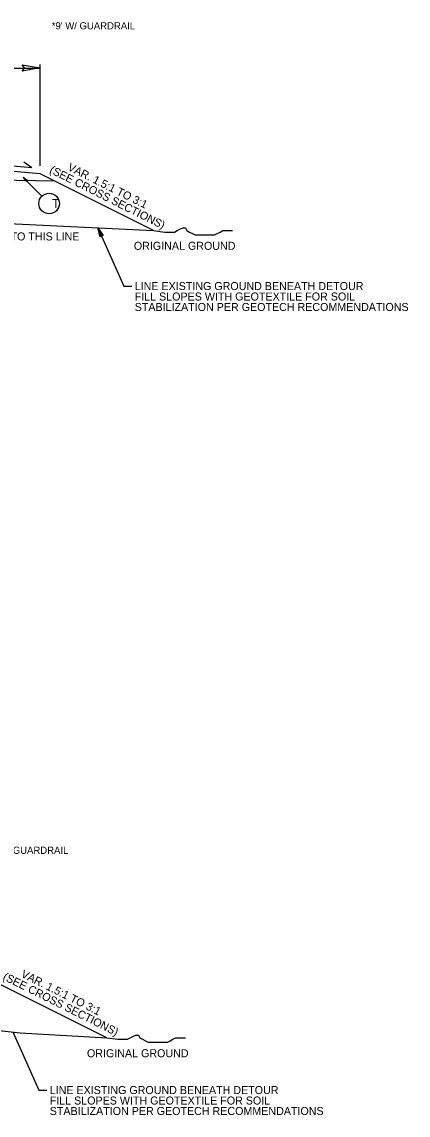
# Model space of a CAD drawing. Extents: x 1548135 to 1549339, y 868664 to 869085.
# Drawn here: x 1548385.7 to 1548422, y 868733.8 to 868836.2 of the extents above; entities that cross this region are included whole.
import ezdxf

# ---------------------------------------------------------------- set-up
doc = ezdxf.new("R2010")
doc.units = 0
for name, color, linetype in [('P_RDY_TC_Pvmt_Asphalt_Base_Course', 7, 'Continuous'), ('Prop Dimension', 7, 'Continuous'), ('Sheet_Data_Field_CELL', 7, 'Continuous'), ('Sheet_Plan', 7, 'Continuous'), ('Typical Grade Point Symbol CELL', 7, 'Continuous'), ('Typical Hinge Slope Interstate CELL', 7, 'Continuous'), ('Typical Pavement Slope Information CELL', 7, 'Continuous'), ('Typical Text General CELL', 7, 'Continuous'), ('Typical Text Grade Point CELL', 7, 'Continuous')]:
    doc.layers.add(name, color=color, linetype=linetype)

msp = doc.modelspace()

# ---------------------------------------------------------------- linework, layer by layer
at = {"layer": 'P_RDY_TC_Pvmt_Asphalt_Base_Course'}
msp.add_lwpolyline([(1548385.78, 868832.2), (1548387.47, 868831.91), (1548385.77, 868831.61), (1548385.98, 868831.91)], close=True, dxfattribs=at)
at = {"layer": 'Prop Dimension'}
for p, q in [((1548398.1, 868816.67), (1548387.47, 868821.99)), ((1548393.7, 868741.02), (1548383.06, 868746.34))]:
    msp.add_line(p, q, dxfattribs=at)
for points in [[(1548398.1, 868816.67), (1548399.14, 868816.54), (1548399.4, 868816.54), (1548399.79, 868816.54), (1548400.05, 868816.54), (1548400.31, 868816.67), (1548400.57, 868816.8), (1548400.83, 868816.93), (1548401.09, 868816.93), (1548401.22, 868816.67), (1548401.48, 868816.54), (1548401.74, 868816.41), (1548401.99, 868816.28), (1548402.25, 868816.28), (1548402.51, 868816.28), (1548402.77, 868816.28), (1548403.03, 868816.28), (1548403.29, 868816.28), (1548403.55, 868816.28), (1548403.81, 868816.28), (1548404.07, 868816.41), (1548404.33, 868816.54), (1548404.59, 868816.67), (1548404.98, 868816.67), (1548405.24, 868816.67), (1548405.5, 868816.67)], [(1548393.7, 868741.02), (1548394.74, 868740.89), (1548395, 868740.89), (1548395.39, 868740.89), (1548395.64, 868740.89), (1548395.9, 868741.02), (1548396.16, 868741.15), (1548396.42, 868741.28), (1548396.68, 868741.28), (1548396.81, 868741.02), (1548397.07, 868740.89), (1548397.33, 868740.76), (1548397.59, 868740.63), (1548397.85, 868740.63), (1548398.11, 868740.63), (1548398.37, 868740.63), (1548398.63, 868740.63), (1548398.89, 868740.63), (1548399.15, 868740.63), (1548399.41, 868740.63), (1548399.66, 868740.76), (1548399.92, 868740.89), (1548400.18, 868741.02), (1548400.57, 868741.02), (1548400.83, 868741.02), (1548401.09, 868741.02)]]:
    msp.add_lwpolyline(points, dxfattribs=at)
at = {"layer": 'Sheet_Plan'}
msp.add_line((1548387.47, 868821.99), (1548383.45, 868822.32), dxfattribs=at)
at = {"layer": 'Typical Grade Point Symbol CELL'}
for p, q in [((1548369.45, 868831.89), (1548387.47, 868831.89)), ((1548387.47, 868822.74), (1548387.47, 868832.25))]:
    msp.add_line(p, q, dxfattribs=at)
at = {"layer": 'Typical Hinge Slope Interstate CELL'}
msp.add_line((1548387.62, 868819.89), (1548385.86, 868821.65), dxfattribs=at)
for points in [[(1548355.45, 868822.88), (1548359.44, 868822.3), (1548362.17, 868821.16), (1548365.07, 868819.48), (1548371.86, 868817.98), (1548383.87, 868817.36), (1548398.1, 868816.67)], [(1548392.88, 868816.92), (1548395.31, 868811.46), (1548396.06, 868811.46)], [(1548323.45, 868752.14), (1548331.96, 868750.47), (1548340.72, 868747.96), (1548348.89, 868746.19), (1548351.53, 868745.5), (1548356.62, 868743.75), (1548363.13, 868743.34), (1548367.71, 868742.31), (1548375.3, 868741.97), (1548381.61, 868741.94), (1548385.59, 868741.51), (1548393.7, 868741.02)], [(1548384.91, 868741.58), (1548387.34, 868736.12), (1548388.09, 868736.12)]]:
    msp.add_lwpolyline(points, dxfattribs=at)
for points in [[(1548386.25, 868821.37), (1548385.86, 868821.65), (1548386.14, 868821.26), (1548386.15, 868821.36)], [(1548393.09, 868816.09), (1548392.88, 868816.92), (1548393.37, 868816.21), (1548393.18, 868816.25)]]:
    msp.add_lwpolyline(points, close=True, dxfattribs=at)
msp.add_circle((1548388.3, 868819.21), 0.962, dxfattribs=at)
at = {"layer": 'Typical Pavement Slope Information CELL'}
for q in [(1548383.8, 868822.8), (1548385.94, 868823.08)]:
    msp.add_line((1548386.69, 868822.56), q, dxfattribs=at)
at = {"layer": 'Typical Text Grade Point CELL'}
msp.add_line((1548381.67, 868821.46), (1548388.81, 868821.32), dxfattribs=at)

# ---------------------------------------------------------------- texts
at = {"layer": 'Sheet_Data_Field_CELL'}
for s, p in [('(SEE CROSS SECTIONS)', (1548388.27, 868822.12)), ('VAR. 1.5:1 TO 3:1', (1548389.97, 868822.37)), ('VAR. 1.5:1 TO 3:1', (1548385.6, 868746.77)), ('(SEE CROSS SECTIONS)', (1548383.9, 868746.52))]:
    msp.add_text(s, height=0.75, rotation=333.434, dxfattribs=at).set_placement(p)
for p in [(1548396.25, 868814.87), (1548391.85, 868739.21)]:
    msp.add_text('ORIGINAL GROUND', height=0.75, dxfattribs=at).set_placement(p)
at = {"layer": 'Typical Hinge Slope Interstate CELL'}
for s, height, p in [('T', 0.861, (1548388.58, 868818.78)), ('GRADE TO THIS LINE', 0.75, (1548380.84, 868815.75)), ('LINE EXISTING GROUND BENEATH DETOUR', 0.75, (1548396.33, 868811.1)), ('STABILIZATION PER GEOTECH RECOMMENDATIONS', 0.75, (1548396.33, 868809.14)), ('FILL SLOPES WITH GEOTEXTILE FOR SOIL', 0.75, (1548396.33, 868810.12)), ('LINE EXISTING GROUND BENEATH DETOUR', 0.75, (1548388.36, 868735.76)), ('FILL SLOPES WITH GEOTEXTILE FOR SOIL', 0.75, (1548388.36, 868734.78)), ('STABILIZATION PER GEOTECH RECOMMENDATIONS', 0.75, (1548388.36, 868733.8))]:
    msp.add_text(s, height=height, dxfattribs=at).set_placement(p)
at = {"layer": 'Typical Text General CELL'}
for p in [(1548388.55, 868835.53), (1548382.29, 868758.27)]:
    msp.add_text("*9' W/ GUARDRAIL", height=0.6682, dxfattribs=at).set_placement(p)

doc.saveas('drawing.dxf')
